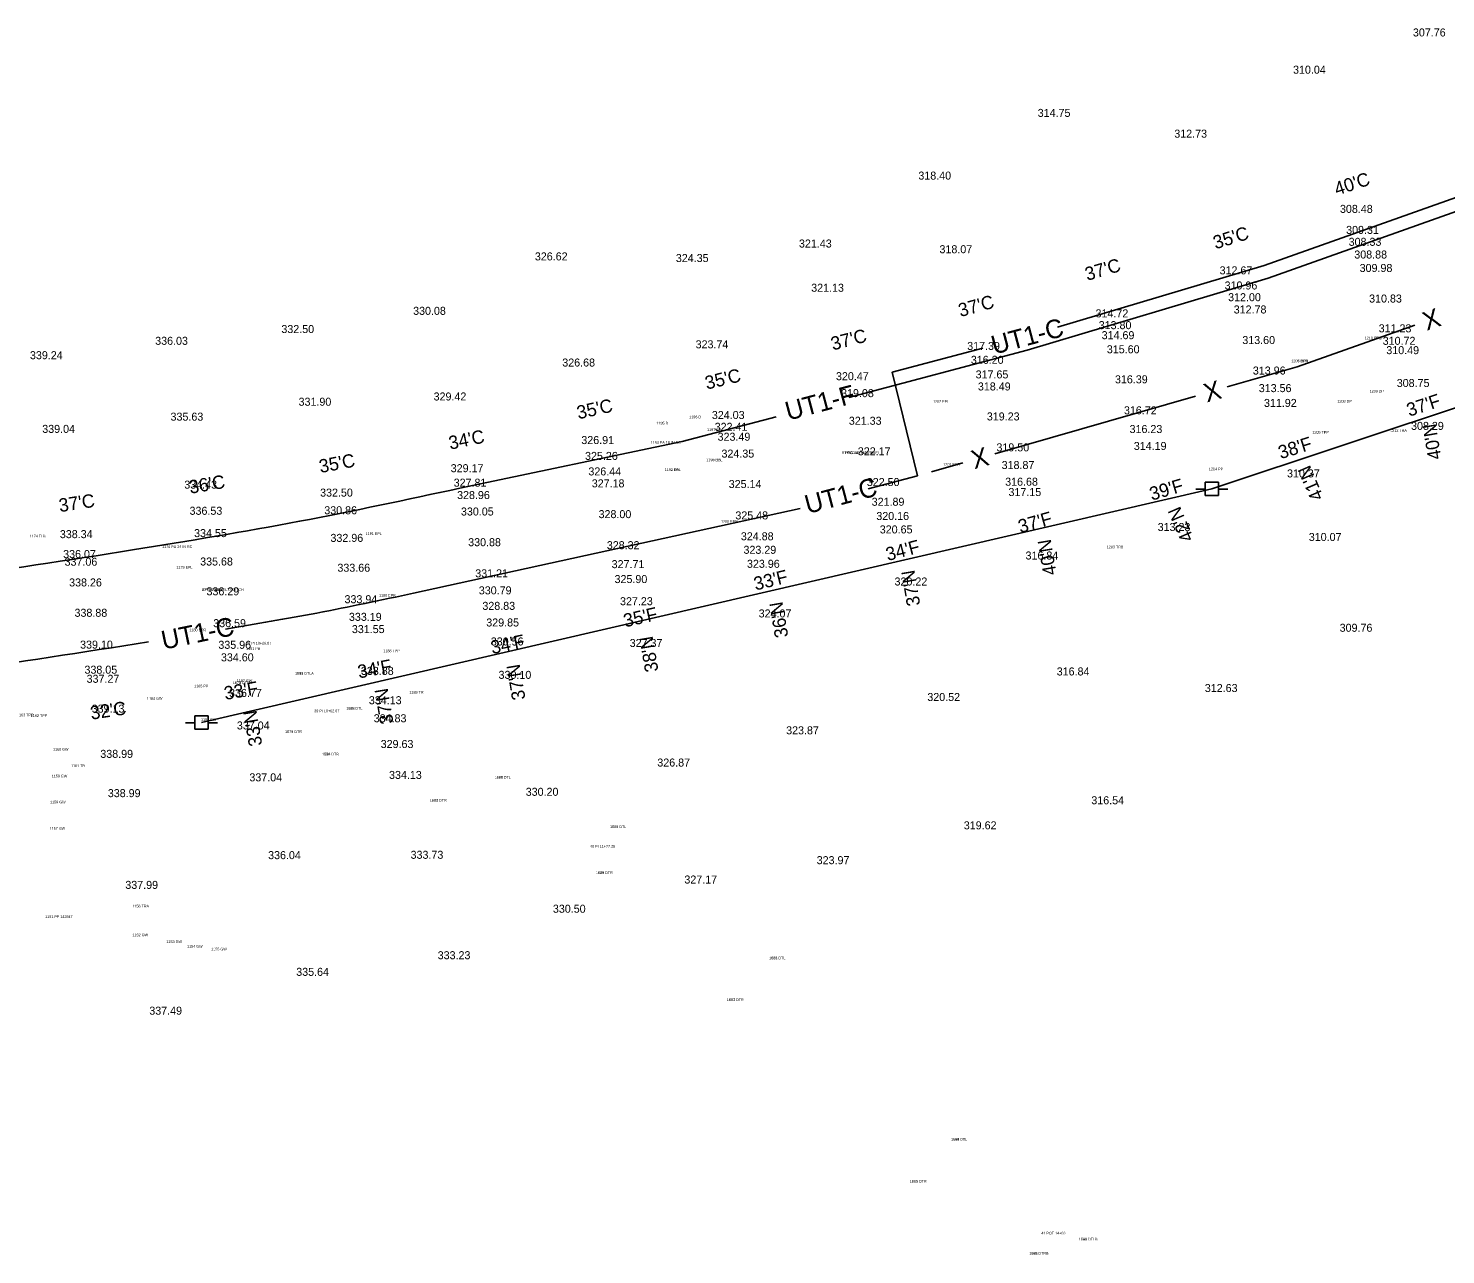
# Model space of a CAD drawing. Extents: x 49683 to 58852, y 49596 to 54801.
# Drawn here: x 51054 to 51586, y 49750 to 50210 of the extents above; entities that cross this region are included whole.
import ezdxf

# ---------------------------------------------------------------- set-up
doc = ezdxf.new("R2010")
doc.units = 0
for name, color, linetype in [('Level 10', 7, 'Continuous'), ('Level 2', 7, 'Continuous'), ('Level 3', 7, 'Continuous'), ('Level 32', 7, 'Continuous'), ('Level 4', 7, 'Continuous'), ('Level 48', 7, 'Continuous'), ('Level 51', 7, 'Continuous'), ('Level 53', 7, 'Continuous'), ('Level 56', 7, 'Continuous'), ('Level 58', 7, 'Continuous'), ('Level 59', 7, 'Continuous'), ('Level 60', 7, 'Continuous'), ('Level 61', 7, 'Continuous'), ('Level 9', 7, 'Continuous')]:
    doc.layers.add(name, color=color, linetype=linetype)

# ---------------------------------------------------------------- blocks, each defined once
blk = doc.blocks.new('PP')
at = {"layer": 'Level 9'}
for p, q in [((2.53, 2.45), (-2.47, 2.45)), ((-2.47, 2.45), (-2.47, -2.55)), ((2.53, -2.55), (2.53, 2.45)), ((-5.91, -0.11), (-2.44, -0.11)), ((-2.47, -2.55), (2.53, -2.55)), ((2.45, -0.11), (6.09, -0.11))]:
    blk.add_line(p, q, dxfattribs=at)

msp = doc.modelspace()

# ---------------------------------------------------------------- linework, layer by layer
at = {"layer": 'Level 10'}
for p in [(51674.22, 50095.74), (51119.33, 49949.54)]:
    msp.add_line(p, (51498.02, 50037.11), dxfattribs=at)
at = {"layer": 'Level 2'}
for p, q in [((51519.2, 50116.09), (51615.33, 50150.2)), ((51428.8, 50089.12), (51519.2, 50116.09)), ((51530.06, 50082.81), (51574.13, 50098.44)), ((51361.94, 50071.36), (51428.8, 50089.12)), ((51503.85, 50075.28), (51530.06, 50082.81)), ((51416.7, 50050.27), (51491.87, 50071.85)), ((51299.58, 50054.8), (51334.74, 50064.14)), ((51216.22, 50037.32), (51299.58, 50054.8)), ((51392.93, 50043.45), (51404.72, 50046.83)), ((51369.21, 50037.08), (51387.72, 50041.99)), ((51198.84, 49998), (51343.7, 50029.67))]:
    msp.add_line(p, q, dxfattribs=at)
for points in [[(50882.95, 49988.03), (50922.2, 49991.68), (51021.03, 50003.3), (51093.49, 50014.19), (51156.12, 50024.93), (51216.22, 50037.32)], [(51128.38, 49984.53), (51162.61, 49990.53), (51198.84, 49998)], [(50797.5, 49946.69), (50810.2, 49947.44), (50925.67, 49956.85), (51025.68, 49968.6), (51099.51, 49979.7)]]:
    msp.add_spline(points, degree=3, dxfattribs=at)
at = {"layer": 'Level 3'}
for p, q in [((51517.65, 50120.85), (51610.67, 50153.85)), ((51440.2, 50097.74), (51517.65, 50120.85)), ((51378.23, 50080.86), (51412.18, 50089.87)), ((51378.23, 50080.86), (51387.72, 50041.99))]:
    msp.add_line(p, q, dxfattribs=at)

# ---------------------------------------------------------------- block references
at = {"layer": 'Level 10'}
for p in [(51498.02, 50037.11), (51119.33, 49949.54)]:
    msp.add_blockref('PP', p, dxfattribs=at)

# ---------------------------------------------------------------- texts
at = {"layer": 'Level 2'}
for s, rotation, p in [('UT1-F', 14.8716, (51339.24, 50062.62)), ('UT1-C', 14.8716, (51346.56, 50027.64)), ('UT1-C', 11.6444, (51105.11, 49976.78))]:
    msp.add_text(s, height=7, rotation=rotation, dxfattribs=at).set_placement(p)
at = {"layer": 'Level 32'}
for s, p in [('307.76', (51573.42, 50206.65)), ('310.04', (51528.49, 50192.69)), ('314.75', (51432.79, 50176.5)), ('312.73', (51483.98, 50168.72)), ('318.40', (51388.06, 50153)), ('308.48', (51546.08, 50140.52)), ('321.43', (51343.31, 50127.54)), ('309.31', (51548.39, 50132.64)), ('308.33', (51549.33, 50128.18)), ('326.62', (51244.32, 50122.71)), ('318.07', (51395.97, 50125.4)), ('308.88', (51551.45, 50123.42)), ('324.35', (51297.16, 50122.1)), ('312.67', (51500.96, 50117.48)), ('309.98', (51553.45, 50118.38)), ('310.96', (51502.83, 50111.82)), ('321.13', (51347.89, 50110.96)), ('312.00', (51504.16, 50107.42)), ('310.83', (51557, 50106.92)), ('330.08', (51198.69, 50102.31)), ('314.72', (51454.47, 50101.36)), ('312.78', (51506.25, 50102.82)), ('313.80', (51455.65, 50096.94)), ('311.23', (51560.58, 50095.75)), ('336.03', (51102.02, 50091.08)), ('332.50', (51149.31, 50095.48)), ('314.69', (51456.76, 50093.19)), ('313.60', (51509.47, 50091.36)), ('310.72', (51562.09, 50091.08)), ('339.24', (51055.08, 50085.68)), ('323.74', (51304.57, 50089.76)), ('317.39', (51406.36, 50089.15)), ('315.60', (51458.7, 50087.9)), ('310.49', (51563.45, 50087.57)), ('326.68', (51254.6, 50082.93)), ('316.20', (51407.73, 50083.95)), ('313.96', (51513.42, 50079.93)), ('320.47', (51357.18, 50077.81)), ('317.65', (51409.52, 50078.48)), ('316.39', (51461.74, 50076.64)), ('308.75', (51567.36, 50075.26)), ('329.42', (51206.37, 50070.21)), ('319.08', (51359.09, 50071.46)), ('318.49', (51410.37, 50073.97)), ('313.56', (51515.64, 50073.34)), ('331.90', (51155.76, 50068.24)), ('316.72', (51465.11, 50065.02)), ('311.92', (51517.58, 50067.79)), ('311.92', (51517.6, 50067.79)), ('335.63', (51107.77, 50062.65)), ('324.03', (51310.66, 50063.26)), ('322.41', (51311.71, 50058.84)), ('321.33', (51362, 50061.11)), ('319.23', (51413.72, 50062.73)), ('308.29', (51572.72, 50059.18)), ('339.04', (51059.69, 50058.06)), ('326.91', (51261.73, 50053.87)), ('323.49', (51312.81, 50055.12)), ('316.23', (51467.22, 50058)), ('325.26', (51263.12, 50047.93)), ('324.35', (51314.27, 50048.8)), ('322.17', (51365.37, 50049.65)), ('319.50', (51417.33, 50051.14)), ('314.19', (51468.8, 50051.66)), ('329.17', (51212.78, 50043.33)), ('318.87', (51419.27, 50044.51)), ('334.43', (51112.92, 50037.17)), ('327.81', (51213.89, 50037.9)), ('326.44', (51264.38, 50042.12)), ('327.18', (51265.64, 50037.64)), ('325.14', (51316.97, 50037.39)), ('322.50', (51368.73, 50038.14)), ('316.68', (51420.59, 50038.26)), ('310.37', (51526.24, 50041.37)), ('332.50', (51163.83, 50034.18)), ('328.96', (51215.17, 50033.26)), ('317.15', (51421.83, 50034.39)), ('336.53', (51114.9, 50027.37)), ('330.86', (51165.39, 50027.56)), ('330.05', (51216.62, 50027.1)), ('321.89', (51370.56, 50030.75)), ('328.00', (51268.2, 50026.11)), ('325.48', (51319.47, 50025.63)), ('320.16', (51372.3, 50025.41)), ('313.23', (51477.75, 50021.29)), ('338.34', (51066.28, 50018.61)), ('334.55', (51116.59, 50019)), ('332.96', (51167.71, 50017.21)), ('324.88', (51321.53, 50017.81)), ('320.65', (51373.59, 50020.38)), ('310.07', (51534.39, 50017.55)), ('336.07', (51067.52, 50011.15)), ('330.88', (51219.33, 50015.59)), ('328.32', (51271.28, 50014.47)), ('323.29', (51322.51, 50012.74)), ('316.84', (51428.23, 50010.6)), ('337.06', (51068.05, 50008.28)), ('335.68', (51118.87, 50008.35)), ('333.66', (51170.31, 50006.02)), ('327.71', (51273.1, 50007.36)), ('323.96', (51323.82, 50007.5)), ('338.26', (51069.76, 50000.51)), ('331.21', (51221.98, 50003.92)), ('325.90', (51274.19, 50001.77)), ('320.22', (51379.13, 50000.86)), ('336.29', (51121.24, 49997.19)), ('330.79', (51223.31, 49997.54)), ('333.94', (51172.98, 49994.22)), ('328.83', (51224.65, 49991.73)), ('327.23', (51276.24, 49993.47)), ('338.88', (51071.78, 49989.14)), ('336.59', (51123.77, 49985.24)), ('333.19', (51174.63, 49987.61)), ('329.85', (51226.11, 49985.5)), ('324.07', (51328.2, 49988.89)), ('331.55', (51175.74, 49983.02)), ('309.76', (51545.96, 49983.52)), ('339.10', (51073.87, 49977.2)), ('335.96', (51125.69, 49977.13)), ('330.56', (51227.8, 49978.38)), ('327.37', (51279.86, 49977.82)), ('334.60', (51126.66, 49972.44)), ('338.05', (51075.51, 49967.8)), ('337.27', (51076.31, 49964.4)), ('333.88', (51179.13, 49967.35)), ('330.10', (51230.71, 49965.87)), ('316.84', (51439.91, 49967.14)), ('336.77', (51129.7, 49959.09)), ('320.52', (51391.42, 49957.57)), ('312.63', (51495.42, 49960.93)), ('339.13', (51078.22, 49953.2)), ('334.13', (51182.1, 49956.36)), ('337.04', (51132.63, 49946.91)), ('334.83', (51183.92, 49949.6)), ('323.87', (51338.5, 49945.08)), ('338.99', (51081.45, 49936.26)), ('329.63', (51186.53, 49939.95)), ('326.87', (51290.22, 49933)), ('337.04', (51137.32, 49927.46)), ('334.13', (51189.66, 49928.36)), ('338.99', (51084.26, 49921.53)), ('330.20', (51240.89, 49922.04)), ('316.54', (51452.88, 49918.86)), ('319.62', (51405.08, 49909.47)), ('336.04', (51144.34, 49898.3)), ('333.73', (51197.74, 49898.43)), ('323.97', (51349.95, 49896.41)), ('327.17', (51300.36, 49889.16)), ('337.99', (51090.82, 49887.15)), ('330.50', (51251.08, 49878.21)), ('333.23', (51207.9, 49860.78)), ('335.64', (51154.88, 49854.55)), ('337.49', (51099.81, 49840))]:
    msp.add_text(s, height=3, dxfattribs=at).set_placement(p)
at = {"layer": 'Level 4'}
for s, rotation, p in [('X', 19.5347, (51578.59, 50096.31)), ('UT1-C', 14.8716, (51416.46, 50087.39)), ('X', 16.0154, (51496.2, 50069.45)), ('X', 16.0154, (51409.05, 50044.43))]:
    msp.add_text(s, height=7, rotation=rotation, dxfattribs=at).set_placement(p)
at = {"layer": 'Level 48'}
for s, rotation, p in [("40'C", 18.1212, (51544.91, 50146.96)), ("35'C", 17.2462, (51499.44, 50126.84)), ("37'C", 16.3712, (51451.35, 50115.02)), ("37'C", 15.4962, (51403.82, 50101.45)), ("37'C", 14.6212, (51356, 50088.93)), ("35'C", 13.6367, (51308.77, 50074.25)), ("37'F", 18.1212, (51572.02, 50064.09)), ("35'C", 12.6367, (51260.65, 50063.13)), ("34'C", 11.6367, (51212.57, 50051.75)), ("38'F", 17.2462, (51523.85, 50048.19)), ("40'N", 99.6367, (51584.14, 50048.45)), ("35'C", 10.6367, (51163.94, 50042.99)), ("41'N", 113.4287, (51540.06, 50033.93)), ("36'C", 9.6367, (51115.16, 50035.22)), ("39'F", 16.3712, (51475.55, 50032.64)), ("37'C", 8.6367, (51066.27, 50028.35)), ("42'N", 113.4287, (51491.38, 50018.46)), ("37'F", 15.4962, (51426.27, 50020.45)), ("34'F", 14.6212, (51376.58, 50010.02)), ("40'N", 99.6367, (51439.9, 50005.14)), ("33'F", 13.6367, (51327.04, 49998.96)), ("37'N", 99.6367, (51388.79, 49993.59)), ("35'F", 12.6367, (51278.13, 49985.17)), ("36'N", 99.6367, (51339.34, 49981.73)), ("34'F", 11.6367, (51228.35, 49975.13)), ("38'N", 99.6367, (51290.66, 49968.84)), ("34'F", 10.6367, (51178.4, 49966)), ("37'N", 99.6367, (51240.83, 49958.34)), ("33'F", 9.6367, (51128.28, 49957.95)), ("37'N", 99.6367, (51191.38, 49949.31)), ("32'C", 8.6367, (51078.08, 49950.55)), ("33'N", 99.6367, (51142.18, 49941.06))]:
    msp.add_text(s, height=5, rotation=rotation, dxfattribs=at).set_placement(p)
at = {"layer": 'Level 51'}
for s, p in [('5 POC 491+43.79 REL', (51359.44, 50050.1)), ('21 PCC 491+43.79', (51359.44, 50050.1)), ('4 POC 488+98.37 DITCH', (51119.51, 49998.84)), ('37 PI 10+00', (51119.51, 49998.84)), ('38 PI 10+26.07', (51136.11, 49978.74)), ('39 PI 10+62.07', (51161.64, 49953.35)), ('40 PI 11+77.25', (51265.01, 49902.57)), ('41 POT 14+00', (51434.14, 49757.61))]:
    msp.add_text(s, height=1, dxfattribs=at).set_placement(p)
at = {"layer": 'Level 53'}
for s, p in [('1211 EPR', (51555.37, 50093.14)), ('1206 EPR', (51527.84, 50084.55)), ('1202 EPL', (51393.53, 50069.34)), ('1199 EPL', (51308.55, 50047.45)), ('1201 EPR', (51397.39, 50045.72)), ('1192 EPL', (51292.96, 50043.75)), ('1200 EPR', (51314.07, 50024.36)), ('1191 EPL', (51180.87, 50019.8)), ('1179 EPL', (51109.95, 50007.17)), ('1190 EPR', (51185.89, 49996.66)), ('1180 EPR', (51114.81, 49983.7))]:
    msp.add_text(s, height=1, dxfattribs=at).set_placement(p)
at = {"layer": 'Level 56'}
for s, p in [('1197 PB', (51308.89, 50058.81)), ('1194 PA 18 IN RC', (51287.68, 50053.97)), ('1176 PA 24 IN RC', (51104.59, 50014.9)), ('1181 PB', (51136.11, 49976.74))]:
    msp.add_text(s, height=1, dxfattribs=at).set_placement(p)
at = {"layer": 'Level 58'}
for s, p in [('1210 DPB', (51555.37, 50093.14)), ('1207 DPA', (51527.84, 50084.55)), ('1209 DP', (51557.18, 50073.19)), ('1208 DP', (51545.11, 50069.42)), ('1195 D', (51289.87, 50061.21)), ('1196 D', (51302.17, 50063.52)), ('1198 DB', (51308.55, 50047.45)), ('1193 DA', (51292.96, 50043.75))]:
    msp.add_text(s, height=1, dxfattribs=at).set_placement(p)
at = {"layer": 'Level 59'}
for s, p in [('1205 TPP', (51535.74, 50057.81)), ('1204 PP', (51496.94, 50044.02)), ('1188 TPP', (51187.51, 49975.87)), ('1185 PP', (51116.64, 49962.66)), ('1187 GW', (51132.56, 49964.69)), ('1184 GW', (51098.9, 49958.01)), ('1163 TPP', (51050.24, 49951.85)), ('1162 TPP', (51055.37, 49951.58)), ('1186 GW', (51119.16, 49950.09)), ('1160 GW', (51063.7, 49938.98)), ('1159 GW', (51063.22, 49928.92)), ('1158 GW', (51062.61, 49919.17)), ('1157 GW', (51062.42, 49909.28)), ('1151 PP 142847', (51060.78, 49876.24)), ('1152 GW', (51093.5, 49869.4)), ('1153 GW', (51106.23, 49866.85)), ('1154 GW', (51113.94, 49865.09)), ('1155 GW', (51123.01, 49864.07))]:
    msp.add_text(s, height=1, dxfattribs=at).set_placement(p)
at = {"layer": 'Level 60'}
for s, p in [('1581 DTLA', (51154.45, 49967.41)), ('1675 DTLA', (51154.45, 49967.41)), ('1578 DTRA', (51131.14, 49963.97)), ('1672 DTRA', (51131.14, 49963.97)), ('1582 DTL', (51173.64, 49954.32)), ('1676 DTL', (51173.64, 49954.32)), ('1579 DTR', (51150.69, 49945.56)), ('1673 DTR', (51150.69, 49945.56)), ('1580 DTR', (51164.57, 49937.15)), ('1674 DTR', (51164.57, 49937.15)), ('1584 DTL', (51229.22, 49928.43)), ('1678 DTL', (51229.22, 49928.43)), ('1583 DTR', (51204.98, 49919.87)), ('1677 DTR', (51204.98, 49919.87)), ('1586 DTL', (51272.5, 49909.94)), ('1680 DTL', (51272.5, 49909.94)), ('1585 DTR', (51267.2, 49892.74)), ('1679 DTR', (51267.2, 49892.74)), ('1588 DTL', (51332.14, 49860.74)), ('1682 DTL', (51332.14, 49860.74)), ('1587 DTR', (51316.29, 49845.11)), ('1681 DTR', (51316.29, 49845.11)), ('1590 DTL', (51400.29, 49792.8)), ('1684 DTL', (51400.29, 49792.8)), ('1589 DTR', (51384.83, 49777.02)), ('1683 DTR', (51384.83, 49777.02)), ('1592 DTLB', (51448.22, 49755.36)), ('1686 DTLB', (51448.22, 49755.36)), ('1591 DTRB', (51429.63, 49750.06)), ('1685 DTRB', (51429.63, 49750.06))]:
    msp.add_text(s, height=1, dxfattribs=at).set_placement(p)
at = {"layer": 'Level 61'}
for s, p in [('1212 TRA', (51564.92, 50058.45)), ('1174 TLB', (51054.93, 50018.86)), ('1203 TRB', (51458.66, 50014.82)), ('1189 TR', (51197.3, 49960.31)), ('1161 TR', (51070.44, 49932.78)), ('1156 TRA', (51093.47, 49880.18))]:
    msp.add_text(s, height=1, dxfattribs=at).set_placement(p)

doc.saveas('drawing.dxf')
